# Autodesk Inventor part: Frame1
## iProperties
Shininess: 64.0
Length Units: 11269
Angle Units: 11279
Time Units: 11290
Mass Units: 11283
Length Display Precision: 3
Angle Display Precision: 2
Compacted: True
Part Number: Frame1
Document SubType Name: Modeling
Created: 2003-02
Material: Standard
Designer: hofer_a
Density: 0.0
Volumn: 0.0
Area: 0.0
PropertySet Name: Model Information
Control State: 0
Master: False
Checked Out: False
Author: hofer_a
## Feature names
1. Extrusion1
2. Bohrung1 [Hole]
3. Extrusion2
4. Extrusion3
5. Extrusion4
6. Rundung1 [Fillet]
7. Extrusion5
8. Bohrung2 [Hole]
9. Extrusion6
10. Extrusion7
11. Extrusion8
